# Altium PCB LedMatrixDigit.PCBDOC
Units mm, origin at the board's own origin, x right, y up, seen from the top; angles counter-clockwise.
Board outline 37.54 x 53.34 mm, 2 copper layers (Top Layer, Bottom Layer); 43 components, 68 nets, 198 pads, 47 vias.
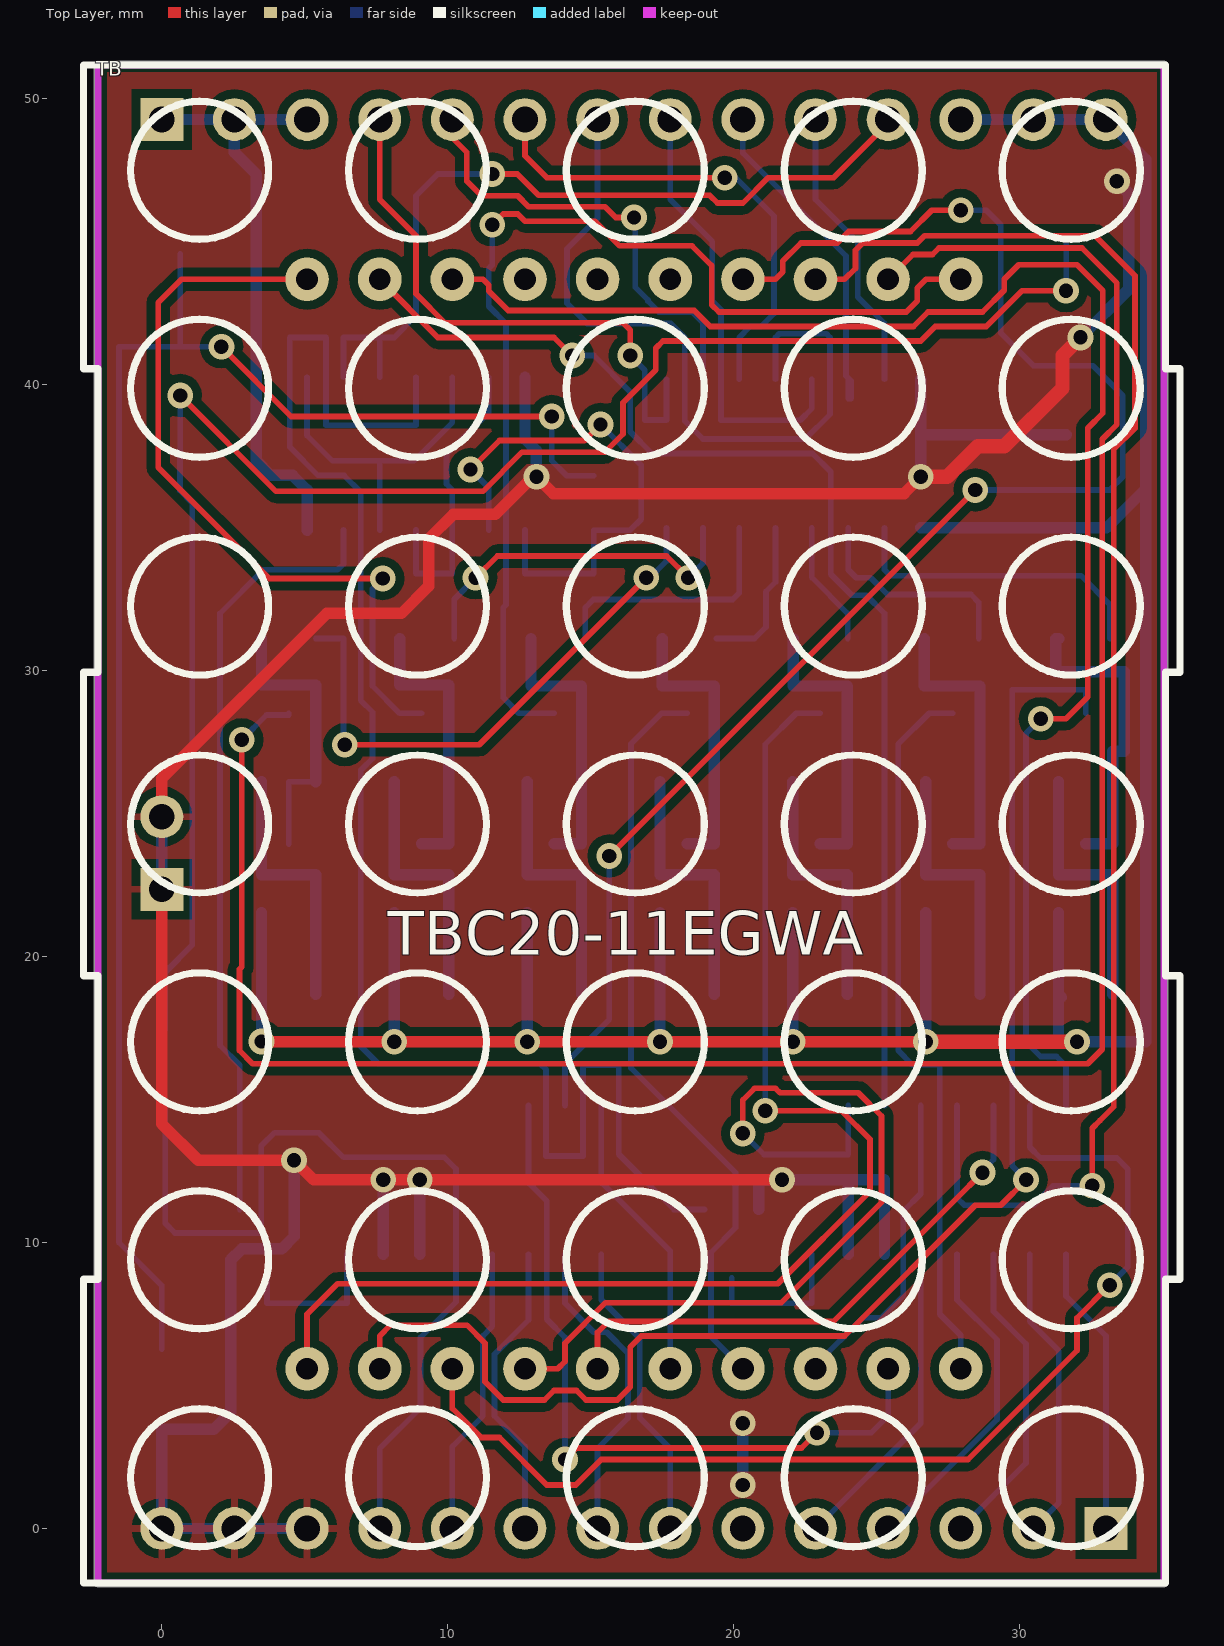
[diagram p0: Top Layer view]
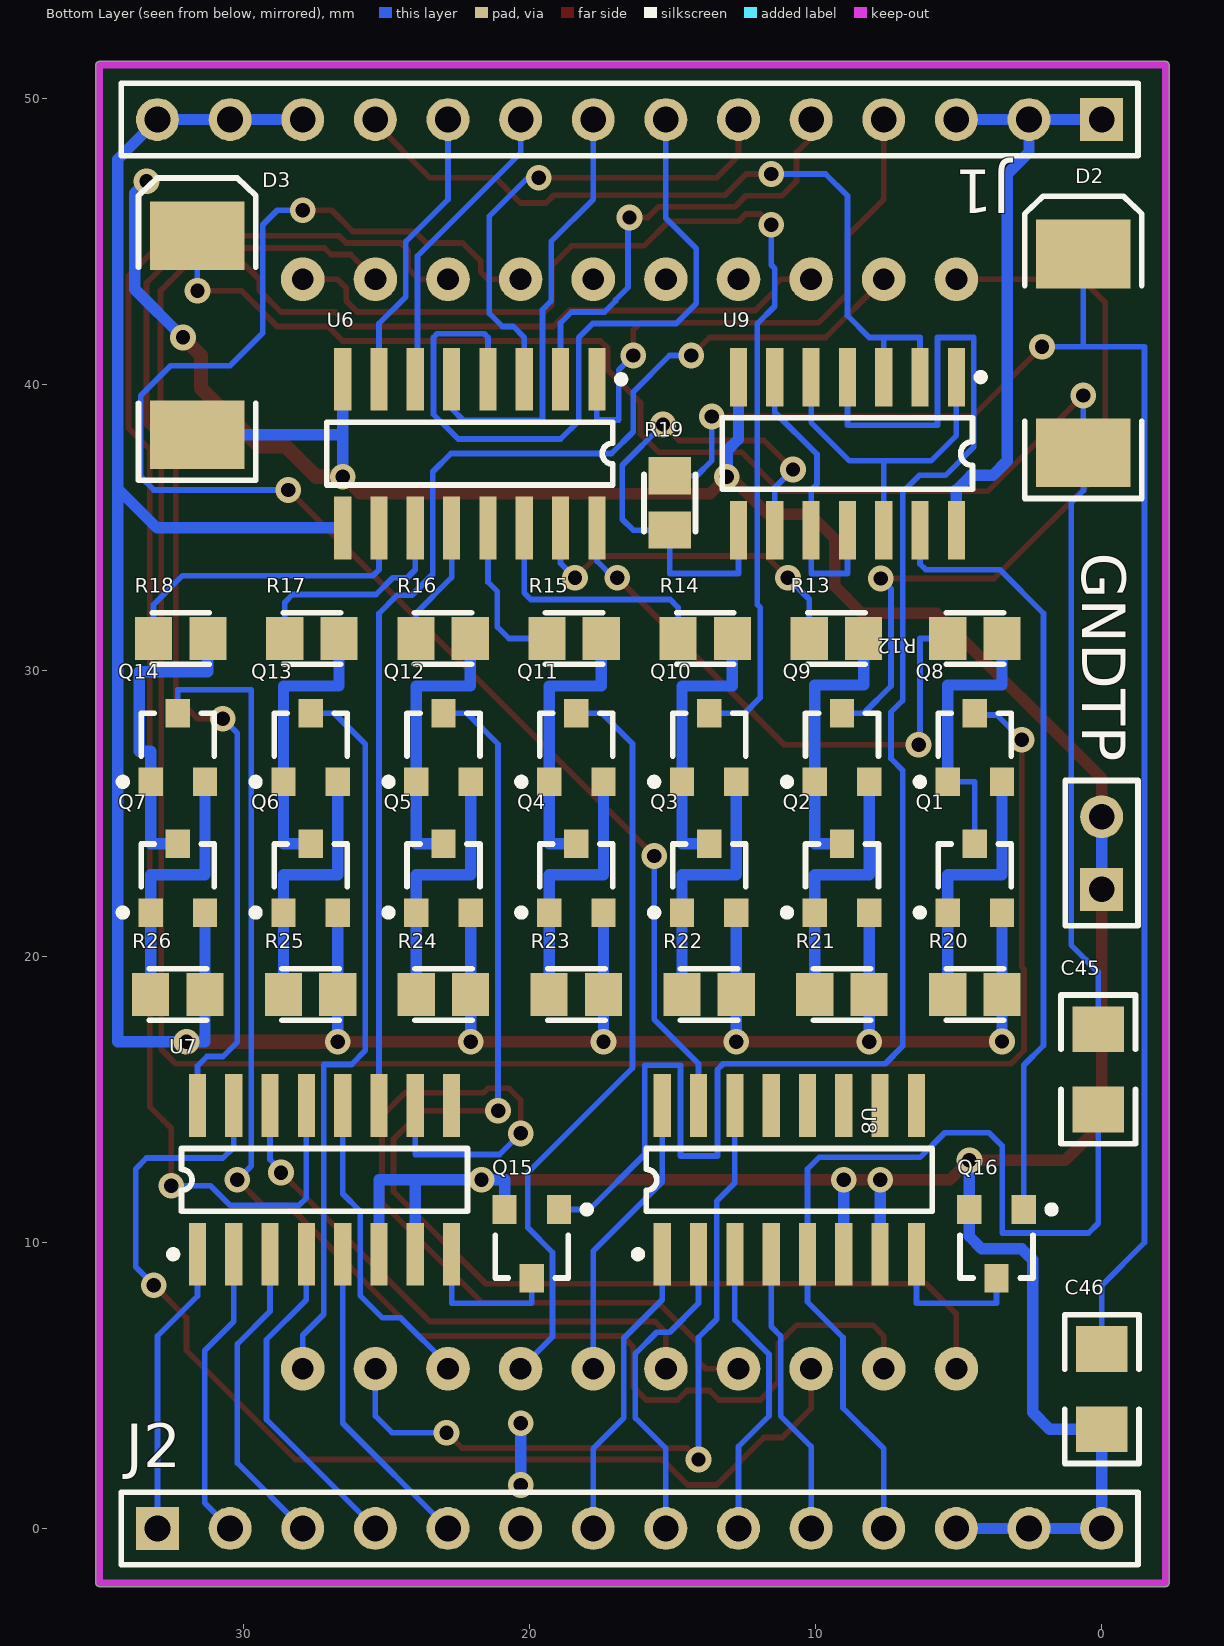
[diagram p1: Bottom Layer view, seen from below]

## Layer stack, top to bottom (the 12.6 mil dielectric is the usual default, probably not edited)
Top Layer: signal copper 0.0356
Dielectric: dielectric 0.32, FR-4, Dk 4.8
Bottom Layer: signal copper 0.0356

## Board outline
-2.363,-1.905 ccw(c-2.235,-1.905) -2.235,-2.032 35.052,-2.032 ccw(c35.052,-1.905) 35.179,-1.905 35.179,51.181 ccw(c35.052,51.181) 35.052,51.308 -2.235,51.308 ccw(c-2.235,51.181) -2.363,51.181

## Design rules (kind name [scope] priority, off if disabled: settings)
Clearance Clearance_PolygonToKeepOut [InPolygon vs OnLayer('Keep-Out Layer')] p1: gap=0.1
Clearance Clearance_Polygon [InPolygon] p2: gap=0.3
Clearance Clearance_PadViaSameNet [IsPad vs IsVia] p3: gap=0.2
Clearance [All] p4: gap=0.2
FabricationTestPointUsage TestPointUsage [All] p1: valid=0 allowmultiple=FALSE
FabricationTestpoint Testpoint [All] p1: side=3 testpointundercomponent=TRUE minsize=1.016 maxsize=2.54 preferedsize=1.524 minholesize=0 maxholesize=1.016 preferedholesize=0.813 testpointgrid=0.025 allowsidetop=TRUE allowsidebottom=TRUE usegrid=TRUE gridtolerance=0
PolygonConnect [All] p1: connectstyle=Relief reliefconductorwidth=0.254 reliefentries=4 polygonreliefangle="90 Angle"
RoomDefinition LedMatrixDigit [InComponentClass('LedMatrixDigit')] p1: confinementstyle=ConfineIn formatcopy=TRUE lockcomponents=FALSE outline -3.302,-2.413 36.068,-2.413 36.068,51.689 -3.302,51.689
RoutingVias [All] p1: holewidth=0.5 width=0.9 viastyle="Through Hole" minholewidth=0.5 minwidth=0.9 maxholewidth=0.5 maxwidth=0.9
SilkscreenOverComponentPads [All] p1: minsilkscreentomaskgap=0.254
SolderMaskExpansion [All] p1: expansion=0.102
Width Width_PolygonTracks [InPolygon] p1: maxlimit=0.3 minlimit=0.2 preferedwidth=0.2
Width Width_PowerNets [InNetClass('POWERNETS')] p2: maxlimit=2.5 minlimit=0.3 preferedwidth=0.4
Width [All] p3: maxlimit=2.5 minlimit=0.2 preferedwidth=0.2
25 further rules are at their usual default settings.

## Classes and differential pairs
net class POWERNETS: 6V GND VCC
net class ROWDRIVER[6..0]: ROWDRIVER0 ROWDRIVER1 ROWDRIVER2 ROWDRIVER3 ROWDRIVER4 ROWDRIVER5 ROWDRIVER6
net class ROW[6..0]: ROW0 ROW1 ROW2 ROW3 ROW4 ROW5 ROW6
net class RED[4..0]: RED0 RED1 RED2 RED3 RED4
net class NROW[6..0]: NROW0 NROW1 NROW2 NROW3 NROW4 NROW5 NROW6
net class GREEN[4..0]: GREEN0 GREEN1 GREEN2 GREEN3 GREEN4

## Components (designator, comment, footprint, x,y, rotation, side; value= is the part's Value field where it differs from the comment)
C45 "0.22uF" C3216-1206 0.119,16.053 r270 bottom
C46 "1.0uF" C3216-1206 -0.008,4.877 r90 bottom
D2 "1N4148" DSO-C2/X3.3 0.643,41.097 r90 bottom
D3 "1N4148" DSO-C2/X3.3 31.631,41.732 r90 bottom
GNDTP "Header 2" HDR1X2 0,22.352 r90 bottom
J1 "Header 14" HDR1X14 0,49.276 r0 bottom
J2 "Header 14" HDR1X14 33.02,0 r180 bottom
Q1 "BC807-40" SOT23 4.435,22.741 r180 bottom
Q2 "BC807-40" SOT23 9.08,22.741 r180 bottom
Q3 "BC807-40" SOT23 13.726,22.741 r180 bottom
Q4 "BC807-40" SOT23 18.372,22.741 r180 bottom
Q5 "BC807-40" SOT23 23.017,22.741 r180 bottom
Q6 "BC807-40" SOT23 27.663,22.741 r180 bottom
Q7 "BC807-40" SOT23 32.309,22.741 r180 bottom
Q8 "BC807-40" SOT23 4.435,27.313 r180 bottom
Q9 "BC807-40" SOT23 9.08,27.313 r180 bottom
Q10 "BC807-40" SOT23 13.726,27.313 r180 bottom
Q11 "BC807-40" SOT23 18.372,27.313 r180 bottom
Q12 "BC807-40" SOT23 23.017,27.313 r180 bottom
Q13 "BC807-40" SOT23 27.663,27.313 r180 bottom
Q14 "BC807-40" SOT23 32.309,27.313 r180 bottom
Q15 "BSH103" SOT23 19.931,9.957 r0 bottom
Q16 "BSH103" SOT23 3.675,9.957 r0 bottom
R12 "1K" CC2012-0805 4.435,31.123 r0 bottom
R13 "1K" CC2012-0805 9.275,31.123 r0 bottom
R14 "1K" CC2012-0805 13.862,31.123 r0 bottom
R15 "1K" CC2012-0805 18.448,31.123 r0 bottom
R16 "1K" CC2012-0805 23.034,31.123 r0 bottom
R17 "1K" CC2012-0805 27.621,31.123 r0 bottom
R18 "1K" CC2012-0805 32.207,31.123 r0 bottom
R19 "1K" CC2012-0805 15.105,35.865 r270 bottom
R20 "3R9" CC2012-0805 4.435,18.677 r0 bottom
R21 "3R9" CC2012-0805 9.08,18.677 r0 bottom
R22 "3R9" CC2012-0805 13.726,18.677 r0 bottom
R23 "3R9" CC2012-0805 18.372,18.677 r0 bottom
R24 "3R9" CC2012-0805 23.017,18.677 r0 bottom
R25 "3R9" CC2012-0805 27.663,18.677 r0 bottom
R26 "3R9" CC2012-0805 32.309,18.677 r0 bottom
TB "TBC20-11EGWA" TBC20-11EGWA 5.08,5.588 r0 top locked
U6 "ULQ2003L" L16 22.098,37.592 r0 bottom
U7 "ULQ2003L" L16 27.178,12.192 r180 bottom
U8 "ULQ2003L" L16 10.922,12.192 r180 bottom
U9 "SN74LVC02AD" D014 8.89,37.592 r0 bottom

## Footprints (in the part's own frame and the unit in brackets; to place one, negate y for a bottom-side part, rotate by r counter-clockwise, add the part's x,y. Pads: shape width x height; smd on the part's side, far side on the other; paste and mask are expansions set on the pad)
C3216-1206 [mm]
  rect 1.6x1.8 smd: 1(-1.403,0) 2(1.397,0)
  silkscreen extent -2.6,-1.3 2.6,1.3
CC2012-0805 [mm]
  rect 1.3x1.5 smd: 1(-0.95,0) 2(0.95,0)
  silkscreen extent -1,-0.9 1,0.9
D014 [mm] "Small Outline; 14 Leads; Body Width 3.9 mm; Pitch 1.27 mm"
  rect 0.6x2.05 smd: 1(-3.81,-2.675) 2(-2.54,-2.675) 3(-1.27,-2.675) 4(0,-2.675) 5(1.27,-2.675) 6(2.54,-2.675) 7(3.81,-2.675) 8(3.81,2.675) 9(2.54,2.675) 10(1.27,2.675) 11(0,2.675) 12(-1.27,2.675) 13(-2.54,2.675) 14(-3.81,2.675)
  silkscreen extent -4.78,-2.8 4.37,1.25
DSO-C2/X3.3 [mm]
  rect 2.4x3.3 smd: 1(-3.475,0) 2(3.475,0)
  silkscreen extent -5.08,-2.05 5.5,2.05
HDR1X2 [mm]
  rect 1.5x1.5 hole 0.9: 1(0,0)
  round 1.5 hole 0.9: 2(2.54,0)
  silkscreen extent -1.27,-1.27 3.81,1.27
HDR1X14 [mm]
  rect 1.5x1.5 hole 0.9: 1(0,0)
  round 1.5 hole 0.9: 2(2.54,0) 3(5.08,0) 4(7.62,0) 5(10.16,0) 6(12.7,0) 7(15.24,0) 8(17.78,0) 9(20.32,0) 10(22.86,0) 11(25.4,0) 12(27.94,0) 13(30.48,0) 14(33.02,0)
  silkscreen extent -1.27,-1.27 34.29,1.27
L16 [mm] "Small Outline; 16 Leads; Body Width 3.9 mm; Pitch 1.27 mm"
  rect 0.6x2.2 smd: 1(-4.445,-2.6) 2(-3.175,-2.6) 3(-1.905,-2.6) 4(-0.635,-2.6) 5(0.635,-2.6) 6(1.905,-2.6) 7(3.175,-2.6) 8(4.445,-2.6) 9(4.445,2.6) 10(3.175,2.6) 11(1.905,2.6) 12(0.635,2.6) 13(-0.635,2.6) 14(-1.905,2.6) 15(-3.175,2.6) 16(-4.445,2.6)
  silkscreen extent -5.42,-2.72 5,1.1
SOT23 [mm] "SOT-23; 3 Leads; Body 3.0 x 2.5 mm, inc. leads (LxW max)"
  rect 0.85x1 smd: 1(-0.95,-1.2) 2(0.95,-1.2) 3(0,1.2)
  silkscreen extent -2.05,-1.32 1.27,1.2
TBC20-11EGWA [mil]
  round 60 hole 30: 1(0,0) 2(100,0) 3(200,0) 4(300,0) 5(400,0) 6(500,0) 7(600,0) 8(700,0) 9(800,0) 10(900,0) 11(900,1500) 12(800,1500) 13(700,1500) 14(600,1500) 15(500,1500) 16(400,1500) 17(300,1500) 18(200,1500) 19(100,1500) 20(0,1500)
  silkscreen extent -308,-295 1202,1795

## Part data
C45 C46: library part CAP, "Capacitor"
D2 D3: library part Diode, "Default Diode"
GNDTP: "Header, 2-Pin"
J1 J2: "Header, 14-Pin"
Q1 Q2 Q3 Q4 Q5 Q6 Q7 Q8 Q9 Q10 Q11 Q12 Q13 Q14: "PNP General-purpose Transistor"
Q15 Q16: "N-channel Enhancement Mode MOSFET"
R12 R13 R14 R15 R16 R17 R18 R19 R20 R21 R22 R23 R24 R25 R26: library part RES, "Resistor"
U6 U7 U8: "High-Voltage, High-Current Darlington Array"
U9: "Quadruple 2-Input Positive-NOR Gate"

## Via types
v1: diameter 0.9, hole 0.5, Top Layer to Bottom Layer, 47 vias

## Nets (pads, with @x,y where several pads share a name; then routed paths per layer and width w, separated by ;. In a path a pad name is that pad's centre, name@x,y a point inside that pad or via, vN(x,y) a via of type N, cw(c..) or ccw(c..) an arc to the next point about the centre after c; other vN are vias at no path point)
6V: J1.12 J1.13 J1.14 Q1.2 Q2.2 Q3.2 Q4.2 Q5.2 Q6.2 Q7.2 R20.1 R21.1 R22.1 R23.1 R24.1 R25.1 R26.1 U6.9 | length 109.7
  Top Layer w0.4: v1@3.495,17.018 v1(26.713,17.018)
  Top Layer w0.5: v1(26.713,17.018) v1(32.004,17.018)
  Bottom Layer w0.4: v1(3.485,17.028) R20.1 Q1.2 ; v1(8.13,17.018) R21.1 Q2.2 ; v1(12.776,17.018) R22.1 12.776,21.514 Q3.2 ; v1(17.422,17.018) R23.1 Q4.2 ; v1(22.067,17.018) R24.1 Q5.2 ; U6.9 33.036,34.992 34.417,36.373 ; v1(26.713,17.018) R25.1 Q6.2 ; J1.12 J1.13 J1.14 34.417,47.879 34.417,17.018 31.359,17.018 Q7.2 ; R26.1 R26.1@31.454,18.582
CG1: TB.18 U7.16 | length 56.1
  Top Layer w0.2: TB.18 11.227,43.688 11.43,43.485 11.43,43.282 12.116,42.596 18.618,42.596 19.177,42.037 26.289,42.037 26.797,42.545 28.702,42.545 29.464,43.307 29.464,43.688 29.972,44.196 32.004,44.196 32.911,43.289 32.911,39.007 32.385,38.481 32.385,29.083 31.623,28.321 v1(30.734,28.321)
  Bottom Layer w0.2: v1(30.734,28.321) 30.226,27.813 30.226,17.018 30.734,16.51 31.293,16.51 31.623,16.18 U7.16
CG2: TB.3 U7.15 | length 38.6
  Top Layer w0.2: TB.3 10.16,4.191 11.173,3.178 11.808,3.178 13.462,1.524 14.478,1.524 15.367,2.413 28.194,2.413 32.004,6.223 32.004,7.366 v1(33.147,8.509)
  Bottom Layer w0.2: U7.15 30.353,13.335 30.734,12.954 33.401,12.954 33.782,12.573 33.782,9.144 v1(33.147,8.509)
CG3: TB.5 U7.14 | length 20.2
  Top Layer w0.2: TB.5 15.24,6.858 15.621,7.239 23.495,7.239 v1(28.702,12.446) 28.24,11.984
  Bottom Layer w0.2: v1(28.702,12.446) 28.702,12.522 29.083,12.903 U7.14
CG4: TB.13 U7.13 | length 53.6
  Top Layer w0.2: TB.13 23.876,43.688 24.257,44.069 24.257,44.704 24.511,44.958 26.416,44.958 26.67,45.212 32.639,45.212 34.036,43.815 34.036,38.481 33.287,37.732 33.287,14.745 32.811,14.27 32.537,13.995 v1(32.537,11.989)
  Bottom Layer w0.2: U7.13 27.813,11.557 28.067,11.303 30.48,11.303 31.166,11.989 v1(32.537,11.989)
CG5: TB.8 U7.12 | length 11.1
  Bottom Layer w0.2: TB.8 22.86,5.715 24.511,7.366 25.146,7.366 25.933,8.153 25.933,11.1 26.543,11.709 U7.12
CR1: TB.19 U7.11 | length 42.6
  Top Layer w0.2: TB.19 9.652,41.656 13.716,41.656 v1(14.351,41.021)
  Bottom Layer w0.2: v1(14.351,41.021) 15.113,41.021 16.383,39.751 16.383,38.354 17.145,37.592 22.758,37.592 23.393,36.957 23.393,33.376 24.13,32.639 24.638,32.639 25.273,32.004 U7.11
CR2: TB.4 U7.10 | length 30.7
  Top Layer w0.2: TB.4 13.843,5.588 14.097,5.842 14.097,6.477 ; 14.166,6.546 14.097,6.477 ; v1(20.32,13.818) 20.32,14.986 20.726,15.392 21.463,15.392 21.615,15.24 24.359,15.24 25.171,14.427 25.171,11.405 21.666,7.899 15.519,7.899 14.097,6.477
  Bottom Layer w0.2: v1(20.32,13.818) 21.057,13.081 24.003,13.081 U7.10
CR3: TB.6 U8.16 | length 10.2
  Bottom Layer w0.2: U8.16 15.367,12.116 17.78,9.703 TB.6
CR4: TB.14 U8.15 | length 55.1
  Top Layer w0.2: v1(15.646,23.52) v1(28.448,36.322) ; TB.14 21.463,43.688 21.717,43.942 21.717,44.323 22.352,44.958 23.622,44.958 24.022,45.358 26.181,45.358 26.924,46.101 v1(27.94,46.101)
  Bottom Layer w0.2: U8.15 14.097,16.256 15.646,17.805 v1(15.646,23.52) ; v1(27.94,46.101) 28.829,46.101 29.337,45.593 29.337,41.808 30.48,40.665 32.563,40.665 33.604,39.624 33.604,36.779 33.147,36.322 v1(28.448,36.322)
CR5: TB.9 U8.14 | length 26.5
  Top Layer w0.2: v1(14.097,2.413) 14.497,2.813 22.371,2.813 v1(22.91,3.352)
  Bottom Layer w0.2: U8.14 12.827,12.09 13.462,11.455 13.462,7.315 14.097,6.68 v1(14.097,2.413) ; v1(22.91,3.352) 24.815,3.352 25.4,3.937 TB.9
ENABLE: J1.11 U9.2 U9.3 | length 28.4
  Top Layer w0.2: v1(11.557,47.371) 12.427,47.371 13.17,46.628 19.158,46.628 19.431,46.355 20.32,46.355 21.209,47.244 23.501,47.244 25.4,49.143 J1.11
  Bottom Layer w0.2: U9.2 6.35,41.656 8.128,41.656 8.89,42.418 8.89,46.609 9.652,47.371 v1(11.557,47.371) ; U9.3 7.62,41.656
GND: C46.1 D3.1 GNDTP.1 GNDTP.2 J2.12 J2.13 J2.14 Q15.2 Q16.2 U6.8 U7.6 U7.7 U8.6 U8.7 U9.7 | length 133.5
  Top Layer w0.4: GNDTP.1 0,14.148 1.27,12.878 v1(4.625,12.878) 5.311,12.192 v1(7.747,12.192) v1(9.017,12.192) v1(21.692,12.192) ; GNDTP.2 0,26.238 5.766,32.004 8.382,32.004 9.329,32.951 9.329,34.602 10.196,35.469 11.669,35.469 12.979,36.779 v1(13.106,36.779) 13.691,36.195 25.959,36.195 v1(26.543,36.779)
  Top Layer w0.5: v1(26.543,36.779) 27.465,36.779 28.532,37.846 29.464,37.846 31.496,39.878 31.496,41.021 v1(32.131,41.656)
  Bottom Layer w0.4: GNDTP.1 GNDTP.2 ; v1(4.625,12.878) Q16.2 4.625,10.213 4.191,9.779 2.794,9.779 2.413,9.398 2.413,4.064 1.823,3.474 C46.1 0,3.466 J2.14 J2.13 J2.12 ; U8.7 v1(7.747,12.192) ; U8.6 v1(9.017,12.192) ; U9.7 12.7,38.1 13.09,37.71 13.09,36.796 v1(13.106,36.779) ; v1(20.32,1.524) v1(20.32,3.683) ; Q15.2 20.881,12.192 v1(21.692,12.192) 24.003,12.192 ; U7.7 24.003,12.192 ; U7.6 25.273,12.192 24.003,12.192 ; v1(26.543,36.779) U6.8 ; 26.543,38.227 26.573,38.257 D3.1 ; v1(32.131,41.656) 33.817,43.342 33.817,46.701 v1(33.401,47.117)
GREEN0: J2.1 U7.1 | length 10.2
  Bottom Layer w0.2: U7.1 31.623,8.128 33.02,6.731 J2.1
GREEN1: J2.2 U7.2 | length 10.4
  Bottom Layer w0.2: U7.2 30.353,7.239 31.369,6.223 31.369,0.889 J2.2
GREEN2: J2.3 U7.3 | length 11
  Bottom Layer w0.2: J2.3 30.226,2.286 30.226,6.452 29.083,7.595 U7.3
GREEN3: J2.4 U7.4 | length 11.7
  Bottom Layer w0.2: J2.4 29.21,3.81 29.21,6.604 27.813,8.001 U7.4
GREEN4: J2.5 U7.5 | length 11.1
  Bottom Layer w0.2: J2.5 26.543,3.683 U7.5
NetC45_1: C45.1 D2.1 D3.2 | length 61
  Top Layer w0.2: v1(0.643,39.624) 3.996,36.271 11.227,36.271 12.598,37.643 15.494,37.643 16.129,38.278 16.129,39.37 17.272,40.513 17.272,41.275 17.526,41.529 26.543,41.529 27.051,42.037 28.829,42.037 30.08,43.288 v1(31.623,43.288)
  Bottom Layer w0.2: C45.1 0.119,19.456 1.067,20.404 1.067,35.865 0.635,36.297 0.635,37.622 D2.1 v1(0.643,39.624) ; v1@31.631,43.296 D3.2
NetC46_2: C46.2 D2.2 R19.1 | length 58.3
  Top Layer w0.2: v1(2.083,41.326) 4.521,38.887 v1(13.64,38.887)
  Bottom Layer w0.2: C46.2 -0.008,8.509 -1.499,10 -1.499,41.326 v1(2.083,41.326) ; 0.643,41.326 D2.2 ; v1(13.64,38.887) 13.64,37.338 14.163,36.815 R19.1
NetQ1_1: Q1.1 Q8.2 R20.2 | length 9.3
  Bottom Layer w0.4: Q8.2 3.485,22.86 5.385,22.86 Q1.1 R20.2
NetQ1_3: Q1.3 Q8.1 R12.1 | length 10
  Bottom Layer w0.2: Q1.3 4.435,26.113 Q8.1
  Bottom Layer w0.4: R12.1 3.485,29.5 5.385,29.5 Q8.1
NetQ2_1: Q2.1 Q9.2 R21.2 | length 9.3
  Bottom Layer w0.4: Q9.2 8.13,22.86 10.03,22.86 Q2.1 R21.2
NetQ2_3: Q2.3 Q9.1 R13.1 | length 9.8
  Bottom Layer w0.4: R13.1 8.325,29.5 10.03,29.5 Q9.1 10.03,23.941 Q2.3
NetQ3_1: Q3.1 Q10.2 R22.2 | length 9.3
  Bottom Layer w0.4: Q10.2 12.776,22.86 14.676,22.86 Q3.1 R22.2
NetQ3_3: Q3.3 Q10.1 R14.1 | length 9.9
  Bottom Layer w0.4: R14.1 12.912,29.464 14.676,29.464 Q10.1 14.676,23.941 Q3.3
NetQ4_1: Q4.1 Q11.2 R23.2 | length 9.3
  Bottom Layer w0.4: Q11.2 17.422,22.86 19.322,22.86 Q4.1 R23.2
NetQ4_3: Q4.3 Q11.1 R15.1 | length 10
  Bottom Layer w0.4: R15.1 17.498,29.464 19.322,29.464 Q11.1 19.322,23.941 Q4.3
NetQ5_1: Q5.1 Q12.2 R24.2 | length 9.3
  Bottom Layer w0.2: Q12.2 Q12.2@22.073,26.113
  Bottom Layer w0.4: Q12.2 22.067,22.86 23.967,22.86 Q5.1 R24.2
NetQ5_3: Q5.3 Q12.1 R16.1 | length 10.1
  Bottom Layer w0.2: R16.1@21.971,31.123 R16.1
  Bottom Layer w0.4: R16.1 22.084,29.464 23.967,29.464 Q12.1 23.967,23.941 Q5.3
NetQ6_1: Q6.1 Q13.2 R25.2 | length 9.3
  Bottom Layer w0.4: Q13.2 26.713,22.86 28.613,22.86 Q6.1 R25.2
NetQ6_3: Q6.3 Q13.1 R17.1 | length 10.1
  Bottom Layer w0.4: R17.1 26.671,29.464 28.613,29.464 Q13.1 28.613,23.941 Q6.3
NetQ7_1: Q7.1 Q14.2 R26.2 | length 9.3
  Bottom Layer w0.4: Q14.2 31.359,22.86 33.259,22.86 Q7.1 R26.2
NetQ7_3: Q7.3 Q14.1 R18.1 | length 11
  Bottom Layer w0.4: R18.1@31.369,31.123 R18.1 31.257,29.957 33.655,29.957 33.655,27.178 33.259,27.178 Q14.1 33.259,23.941 Q7.3
NetQ15_1: Q15.1 U9.4 | length 58.3
  Bottom Layer w0.2: U9.4 8.89,38.583 5.74,38.583 5.74,41.656 4.47,41.656 4.47,37.821 5.461,36.83 6.375,36.83 6.96,36.246 6.96,28.956 7.366,28.55 7.366,26.924 6.96,26.518 6.96,16.866 7.569,16.256 13.233,16.256 13.437,16.053 13.437,13.03 14.732,13.03 14.732,16.205 15.977,16.205 15.977,13.087 17.907,11.157 Q15.1
NetQ15_3: Q15.3 U7.8 | length 5.4
  Bottom Layer w0.2: Q15.3 19.931,7.874 22.733,7.874 U7.8
NetQ16_1: Q16.1 U9.13 | length 27.4
  Bottom Layer w0.2: Q16.1 2.725,16.198 2.032,16.891 2.032,32.004 3.556,33.528 6.147,33.528 6.35,33.731 U9.13
NetQ16_3: Q16.3 U8.8 | length 5.4
  Bottom Layer w0.2: Q16.3 3.675,7.882 6.477,7.882 U8.8
NetR19_2: R19.2 U9.8 U9.9 | length 18.7
  Top Layer w0.2: v1(10.795,37.033) 11.811,38.049 14.783,38.049 v1(15.342,38.608)
  Bottom Layer w0.2: v1(10.795,37.033) 11.43,36.398 U9.9 ; U9.8 12.7,33.401 15.105,33.401 R19.2 16.383,34.915 16.764,35.296 16.764,37.186 v1(15.342,38.608)
NetU9_1: U9.1 U9.5 U9.12 | length 12
  Bottom Layer w0.2: U9.1 5.08,38.227 5.969,37.338 7.62,37.338 ; U9.12 7.62,37.338 ; U9.5 10.16,38.684 8.814,37.338 7.62,37.338
NetU9_6: U9.6 U9.10 U9.11 | length 10.3
  Bottom Layer w0.2: U9.11 8.89,33.401 10.16,33.401 10.16,36.322 9.957,36.525 9.957,37.567 11.43,39.04 U9.6
NROW0: R12.2 U6.16 | length 19.7
  Top Layer w0.2: v1(6.401,27.407) 11.1,27.407 v1(16.942,33.249)
  Bottom Layer w0.2: R12.2 6.35,31.123 v1@6.35,27.432 ; v1(16.942,33.249) 17.069,33.249 17.653,33.833 U6.16
NROW1: R13.2 U6.15 | length 12.5
  Top Layer w0.2: v1(10.973,33.249) 11.735,34.011 17.653,34.011 v1(18.415,33.249)
  Bottom Layer w0.2: R13.2 10.225,32.501 v1(10.973,33.249) ; v1(18.415,33.249) 18.923,33.757 U6.15
NROW2: R14.2 U6.14 | length 9
  Bottom Layer w0.2: R14.2 14.812,32.211 15.088,32.487 19.964,32.487 20.193,32.715 U6.14
NROW3: R15.2 U6.13 | length 5.5
  Bottom Layer w0.2: R15.2 20.726,31.123 21.133,31.529 21.133,32.766 21.463,33.096 U6.13
NROW4: R16.2 U6.12 | length 4.4
  Bottom Layer w0.2: U6.12 22.733,33.255 23.984,32.004 R16.2
NROW5: R17.2 U6.11 | length 7.8
  Bottom Layer w0.2: U6.11 24.003,33.528 24.283,33.248 24.791,33.248 25.375,32.664 28.296,32.664 28.571,32.389 R17.2
NROW6: R18.2 U6.10 | length 11
  Bottom Layer w0.2: U6.10 25.273,33.528 25.476,33.325 32.141,33.325 33.157,32.309 R18.2
RED0: J2.7 U8.1 | length 10.6
  Bottom Layer w0.2: U8.1 15.367,8.001 16.713,6.655 16.713,3.861 17.78,2.794 J2.7
RED1: J2.8 U8.2 | length 11.2
  Bottom Layer w0.2: U8.2 14.097,7.874 15.105,6.866 15.562,6.866 16.307,6.121 16.307,3.861 15.24,2.794 J2.8
RED2: J2.9 U8.3 | length 10.5
  Bottom Layer w0.2: J2.9 12.7,2.87 11.633,3.937 11.633,6.096 12.827,7.29 U8.3
RED3: J2.10 U8.4 | length 10.2
  Bottom Layer w0.2: J2.10 10.16,2.87 11.227,3.937 11.227,6.731 11.557,7.061 U8.4
RED4: C45.2 J2.11 U8.5 | length 31.7
  Bottom Layer w0.2: C45.2 0.119,10.676 0.457,10.338 3.48,10.338 3.48,13.386 3.937,13.843 5.486,13.843 6.35,12.979 9.881,12.979 10.287,12.573 U8.5 10.287,7.925 9.042,6.68 9.042,4.216 7.62,2.794 J2.11
ROW0: J1.4 U6.1 | length 20.2
  Top Layer w0.2: J1.4 7.62,46.482 8.89,45.212 8.89,43.18 9.906,42.164 16.129,42.164 16.383,41.91 v1(16.383,41.021)
  Bottom Layer w0.2: v1(16.383,41.021) 16.891,40.513 16.891,38.767 17.653,38.767 U6.1
ROW1: J1.5 U6.2 | length 16.1
  Top Layer w0.2: J1.5 10.16,48.635 10.668,48.127 10.668,47.117 11.176,46.609 12.446,46.609 12.827,46.228 15.494,46.228 15.875,45.847 v1(16.51,45.847)
  Bottom Layer w0.2: v1(16.51,45.847) 16.561,45.796 16.561,43.406 17.004,42.963 17.004,42.924 17.383,42.545 18.542,42.545 18.923,42.164 U6.2
ROW2: J1.6 U6.3 | length 17.3
  Top Layer w0.2: J1.6 12.7,48.006 13.462,47.244 v1(19.685,47.244)
  Bottom Layer w0.2: v1(19.685,47.244) 20.066,47.244 21.412,45.898 21.412,42.494 20.955,42.037 20.574,42.037 20.193,41.656 U6.3
ROW3: J1.7 U6.4 | length 26.3
  Bottom Layer w0.2: J1.7 15.24,45.822 14.173,44.755 14.173,42.85 14.878,42.145 17.799,42.145 18.288,41.656 18.288,38.735 18.923,38.1 22.504,38.1 23.368,38.964 23.368,41.656 23.241,41.783 21.59,41.783 21.463,41.656 U6.4
ROW4: J1.8 U6.5 | length 15.6
  Bottom Layer w0.2: J1.8 17.78,46.482 19.253,45.009 19.253,42.926 19.558,42.621 19.558,38.76 22.327,38.76 22.733,39.167 U6.5
ROW5: J1.9 U6.6 | length 12.1
  Bottom Layer w0.2: J1.9 20.32,48.108 23.927,44.501 23.927,40.31 24.024,40.213 24.105,40.132 24.105,39.522 24.003,39.522 U6.6
ROW6: J1.10 U6.7 | length 10.1
  Bottom Layer w0.2: J1.10 22.86,46.482 24.333,45.009 24.333,43.078 25.273,42.139 U6.7
ROWDRIVER0: Q8.3 TB.12 | length 79.5
  Top Layer w0.2: v1(2.794,27.584) 2.794,19.634 2.718,19.558 2.718,16.713 3.175,16.256 32.385,16.256 32.887,16.758 32.887,38.094 33.401,38.608 33.401,43.561 32.182,44.78 27.178,44.78 26.956,44.558 26.27,44.558 TB.12
  Bottom Layer w0.2: v1(2.794,27.584) 3.658,28.448 4.435,28.448 Q8.3
ROWDRIVER1: Q9.3 TB.20 | length 26.8
  Top Layer w0.2: TB.20 0.686,43.688 -0.127,42.875 -0.127,37.109 3.759,33.223 v1(7.722,33.223)
  Bottom Layer w0.2: v1(7.722,33.223) 7.366,32.868 7.366,29.464 8.317,28.513 Q9.3
ROWDRIVER2: Q10.3 TB.11 | length 38.7
  Top Layer w0.2: v1(11.557,45.593) 11.938,45.974 12.446,45.974 12.7,45.72 15.138,45.72 16.002,44.856 18.542,44.856 19.228,44.171 19.228,42.799 19.482,42.545 26.035,42.545 26.416,42.926 26.416,43.379 26.725,43.688 TB.11
  Bottom Layer w0.2: v1@11.792,45.358 v1(11.557,45.593) 11.557,44.196 11.43,44.069 11.43,42.748 12.04,42.139 12.04,32.309 11.938,32.207 11.938,29.058 12.483,28.513 Q10.3
ROWDRIVER3: Q11.3 TB.7 | length 26.6
  Bottom Layer w0.2: Q11.3 17.475,28.513 16.408,27.446 16.408,16.104 20.066,12.446 20.066,10.516 19.202,9.652 19.202,6.706 TB.7
ROWDRIVER4: Q12.3 TB.1 | length 44.4
  Top Layer w0.2: TB.1 5.08,7.493 6.147,8.56 21.539,8.56 24.765,11.786 24.765,13.614 23.774,14.605 v1(21.107,14.605)
  Bottom Layer w0.2: v1(21.107,14.605) 21.107,27.432 22.188,28.513 Q12.3
ROWDRIVER5: Q13.3 TB.10 | length 25.7
  Bottom Layer w0.2: Q13.3 26.837,28.513 25.756,27.432 25.756,16.713 26.238,16.231 27.203,16.231 27.203,7.493 27.94,6.756 TB.10
ROWDRIVER6: Q14.3 TB.2 | length 50.8
  Top Layer w0.2: TB.2 7.62,6.731 8.001,7.112 10.668,7.112 11.303,6.477 11.303,5.131 11.938,4.496 13.386,4.496 13.716,4.826 14.5,4.826 14.83,4.496 15.926,4.496 16.383,4.953 16.383,6.35 16.764,6.731 23.876,6.731 28.448,11.303 29.337,11.303 v1(30.226,12.192)
  Bottom Layer w0.2: v1(30.226,12.192) 29.743,12.675 29.743,29.337 32.309,29.337 Q14.3
VCC: J1.1 J1.2 J1.3 U9.14 | length 20.9
  Bottom Layer w0.4: J1.1 J1.2 ; U9.14 5.08,36.322 4.572,36.83 3.81,36.83 3.302,37.338 3.302,47.371 2.54,48.133 J1.2 ; J1.3 J1.2
pads on no net: J2.6 TB.15 TB.16 TB.17 U7.9 U8.9 U8.10 U8.11 U8.12 U8.13

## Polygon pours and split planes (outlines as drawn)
GND on Top Layer "Top Layer-GND" (solid, remove dead copper, pour order 1000): -2.032,50.927 34.798,50.927 34.798,-1.524 -1.905,-1.524 -1.905,50.927

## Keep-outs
Keep-Out Layer:
  lines w0.254: -2.235,-1.905 -2.235,51.181 35.052,51.181 35.052,-1.905 -2.235,-1.905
